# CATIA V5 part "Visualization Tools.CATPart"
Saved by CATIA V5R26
Part number: Visualization Tools
Bounding box of the stored display mesh (mm): x 766.7 to 1406.053, y -781.992 to -669.565, z 394.641 to 524.096
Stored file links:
  D:\LinkedIn Learning\NURBS\CATIA\Class Parts\Visualization Tools.CATPart
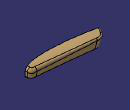
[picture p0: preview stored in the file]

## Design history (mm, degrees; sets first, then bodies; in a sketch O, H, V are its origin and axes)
AxisSystem1: origin (0, 0, 0), X (1, 0, 0), Y (0, 1, 0), Z (0, 0, 1)
Set1
  DatumSurface1
Body1 (main body)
